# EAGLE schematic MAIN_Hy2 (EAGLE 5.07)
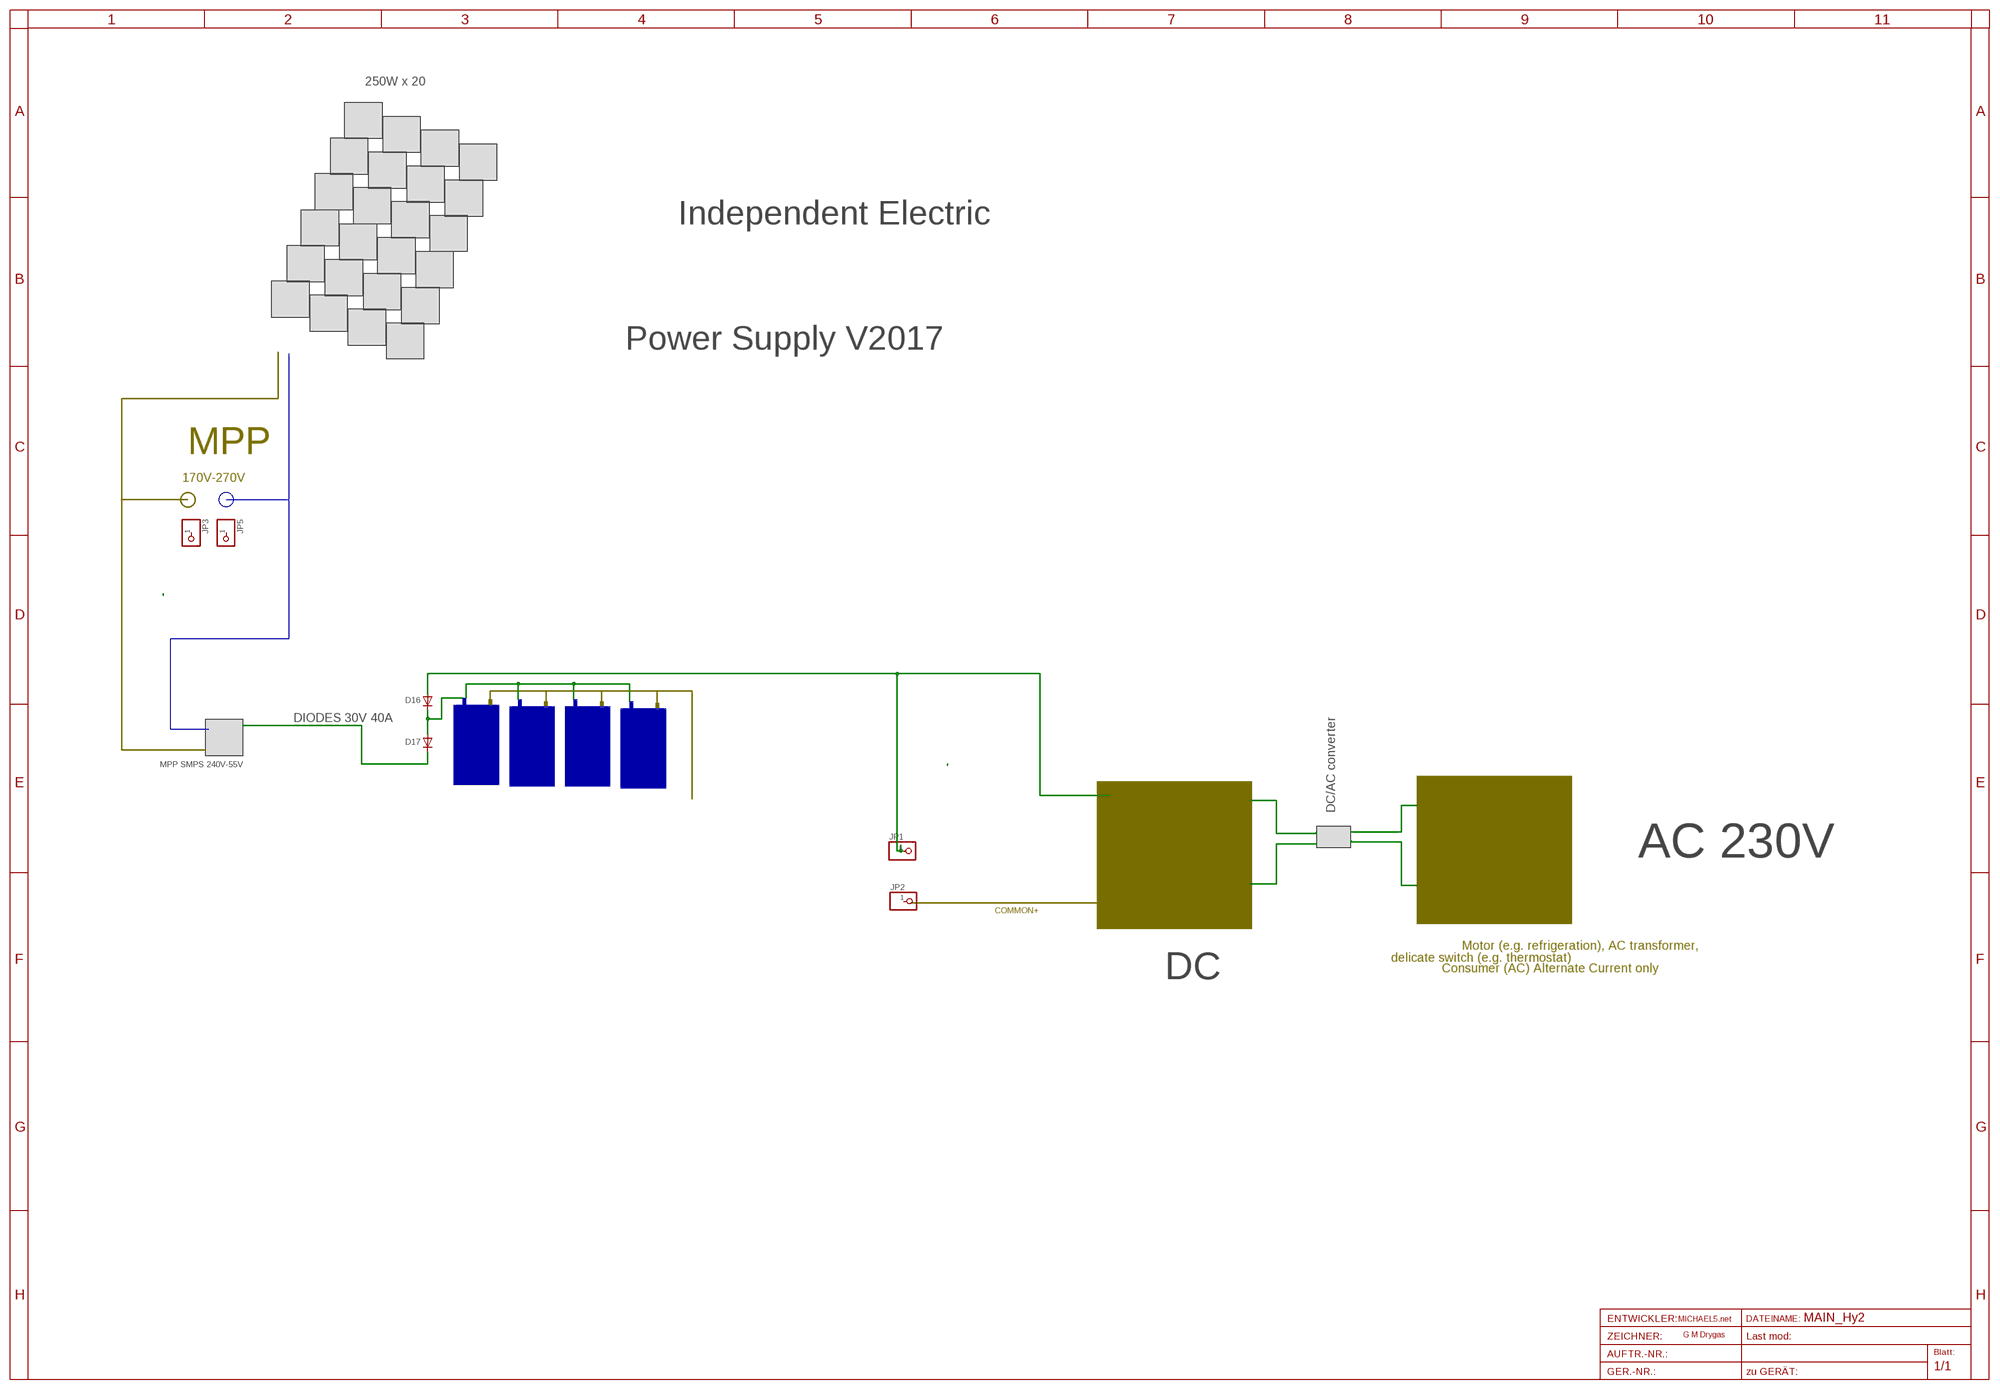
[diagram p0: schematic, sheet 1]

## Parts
D16  DIODE-SMC  [SMC]
D17  DIODE-SMC  [SMC]
JP1  PINHD-1X14.5MM  [1X4MM5]
JP2  PINHD-1X14.5MM  [1X4MM5]
JP3  PINHD-1X14.5MM  [1X4MM5]
JP5  PINHD-1X14.5MM  [1X4MM5]

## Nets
N$17: JP1.1
N$19: D16.C D17.A
N$21: D17.C
Unconnected: D16.A JP2.1 JP3.1 JP5.1

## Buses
B$1
B$2

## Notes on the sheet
- 250W x 20
- Independent Electric
- Power Supply V2017
- MPP
- 170V-270V
- DIODES 30V 40A
- MPP SMPS 240V-55V
- DC/AC converter
- AC 230V
- COMMON+
- Motor (e.g. refrigeration), AC transformer,
- delicate switch (e.g. thermostat) | Consumer (AC) Alternate Current only
- DC
- MICHAEL5.net
- G M Drygas

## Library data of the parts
D16 D17 = diode:DIODE-: DIODE
JP1-JP3 JP5 = pinhead:PINHD-1X1: PIN HEADER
